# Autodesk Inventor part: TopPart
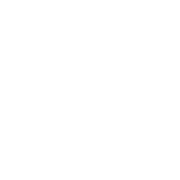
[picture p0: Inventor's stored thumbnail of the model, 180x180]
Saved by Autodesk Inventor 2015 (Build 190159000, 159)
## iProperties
Created: 2016-02
Part Number: TopPart
Material: Wood (Birch)
Document SubType Name: Modeling
Designer: Hafliði
Density: 0.55 g/cm^3
Appearance: Birch - Natural Polished
Mass: 2725.94 g
Surface Area: 4411.5 cm^2
Volume: 4956.25 cm^3
Author: Hafliði
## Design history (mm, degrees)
sketch "Sketch1"
  geometry: L1 (-160, 267.5)-(160, 267.5); L2 (160, 267.5)-(160, -267.5); L3 (160, -267.5)-(-160, -267.5); L4 (-160, -267.5)-(-160, 267.5); L5 (-160, 267.5)-(160, -267.5); L6 (160, 267.5)-(-160, -267.5); 1 further point
  constraints: 12 end point, 2 midpoint, 2 parallel, 1 horizontal, 1 perpendicular
  dimensions: "d0" = 320 distance of L2.end L3.end; "d1" = 535 distance of L1.end L2.end
extrude "Extrusion1" new body sketch "Sketch1" distance "d2" = 50; taper "d3" = 0 deg
sketch "Sketch2"
  geometry: L1 (-135, 240)-(135, 240); L2 (135, 240)-(135, -240); L3 (135, -240)-(-135, -240); L4 (-135, -240)-(-135, 240); L5 (-135, 240)-(135, -240); L6 (135, 240)-(-135, -240); 1 further point
  constraints: 12 end point, 2 midpoint, 2 parallel, 1 horizontal, 1 perpendicular
extrude "Extrusion2" cut sketch "Sketch2" distance "d4" = 25; taper "d5" = 0 deg
sketch "Sketch3"
  geometry: L1 (-160, 267.5)-(-160, 0); L2 (-160, 267.5)-(-160, -267.5) reference; L3 (-232, 75)-(-88, 75); L4 (-88, 75)-(-88, -75); L5 (-88, -75)-(-232, -75); L6 (-232, -75)-(-232, 75); L7 (-232, 75)-(-88, -75); L8 (-88, 75)-(-232, -75); 1 further point
  constraints: 14 end point, 3 midpoint, 2 parallel, 1 horizontal, 1 perpendicular
  dimensions: "d6" = 150 distance of L3.end L4.end; "d7" = 144 distance of L4.end L5.end
extrude "Extrusion3" cut sketch "Sketch3" distance "d8" = 50; taper "d9" = 0 deg
body "Solid1"
